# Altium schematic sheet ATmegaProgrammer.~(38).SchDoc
size A4
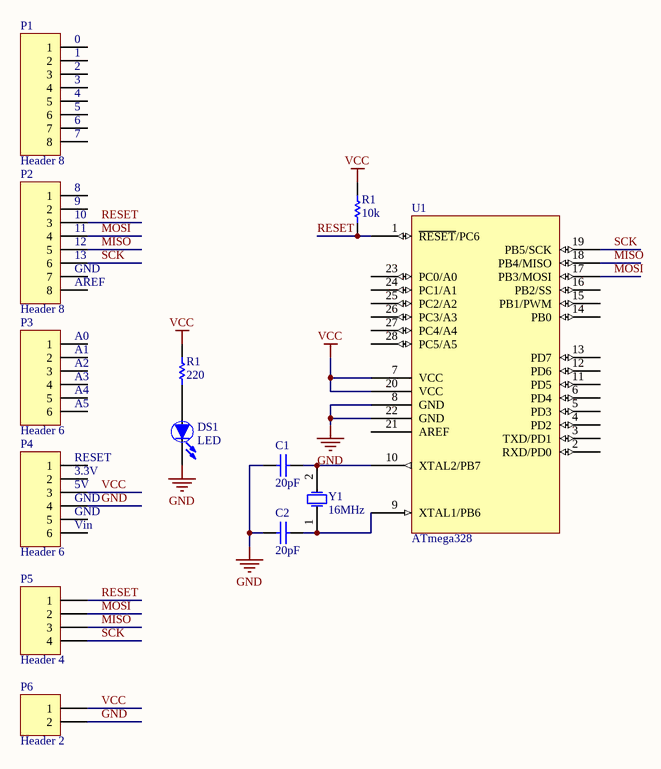
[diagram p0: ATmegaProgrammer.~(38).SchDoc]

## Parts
(Parts that share a designator on the sheet are numbered #1, #2 ... from top to bottom, then left to right.)
C1  20pF  [C200]
C2  20pF  [C200]
DS1  LED  [LED-3mm_G]
P1  Header 8  [HDR1X8]
P2  Header 8  [HDR1X8]
P3  Header 6  [HDR1X6]
P4  Header 6  [HDR1X6]
P5  Header 4  [HDR1X4]
P6  Header 2  [HDR1X2]
R1#1  10k  [AXIAL-0.3]
R1#2  220  [AXIAL-0.3]
U1  ATmega328  [DIP28]
Y1  16MHz  [XTAL4-8]

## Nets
GND: C1.1 C2.1 DS1.2(K) P4.4 P6.2 U1.8(GND) U1.22(GND)
VCC: P4.3 P6.1 R1#1.2 R1#2.2 U1.7(VCC) U1.20(VCC)
MISO: P2.5 P5.3 U1.18(PB4/MISO)
MOSI: P2.4 P5.2 U1.17(PB3/MOSI)
RESET: P2.3 P5.1 R1#1.1 U1.1(~{RESET}/PC6)
SCK: P2.6 P5.4 U1.19(PB5/SCK)
NetC1_2: C1.2 U1.10(XTAL2/PB7) Y1.2(OSC2)
NetC2_2: C2.2 U1.9(XTAL1/PB6) Y1.1(OSC1)
NetDS1_1: DS1.1(A) R1#2.1

Not connected (* = marked no-connect by the designer): P1 1 2 3 4 5 6 7 8; P2 1 2 7 8; P3 1 2 3 4 5 6; P4 1 2 5 6; U1 2(RXD/PD0) 3(TXD/PD1) 4(PD2) 5(PD3) 6(PD4) 11(PD5) 12(PD6) 13(PD7) 14(PB0) 15(PB1/PWM) 16(PB2/SS) 21(AREF) 23(PC0/A0) 24(PC1/A1) 25(PC2/A2) 26(PC3/A3) 27(PC4/A4) 28(PC5/A5)

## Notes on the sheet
- (near P1) 0
- (near P1) 1
- (near P1) 2
- (near P1) 3
- (near P1) 4
- (near P1) 5
- (near P1) 6
- (near P1) 7
- (near P2) 8
- (near P2) 9
- (near P2) 10
- (near P2) 11
- (near P2) 12
- (near P2) 13
- (near P2) GND
- (near P2) AREF
- (near P3) A0
- (near P3) A1
- (near P3) A2
- (near P3) A3
- (near P3) A4
- (near P3) A5
- (near P4) RESET
- (near P4) 3.3V
- (near P4) 5V
- (near P4) GND
- (near P4) Vin

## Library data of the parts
C1 C2 = Cap: Capacitor
DS1 = LED: Typical INFRARED GaAs LED
P1 P2 = Header 8: Header, 8-Pin
P3 P4 = Header 6: Header, 6-Pin
P5 = Header 4: Header, 4-Pin
P6 = Header 2: Header, 2-Pin
R1#1 R1#2 = Res: Resistor
U1 = ATmega328: ATmega¨t¦C³æ´¹¤ù
Y1 = XTAL: Crystal Oscillator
